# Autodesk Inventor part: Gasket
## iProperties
Created: 2007-11
Part Number: Gasket
Document SubType Name: Modeling
Designer: CM
Density: 1 g/cm^3
Mass: 0.815318 g
Surface Area: 68.2866 cm^2
Volume: 0.815318 cm^3
Author: CM
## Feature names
1. Fillet1
2. Hole1
